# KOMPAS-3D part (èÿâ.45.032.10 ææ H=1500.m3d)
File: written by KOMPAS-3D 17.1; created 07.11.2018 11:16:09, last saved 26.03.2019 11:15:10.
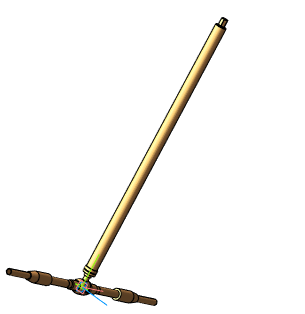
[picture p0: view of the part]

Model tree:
1. Операция без истории:2  (with: Сечение модели:1)  (labels: Сталь 20  ГОСТ 1050-2013)

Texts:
  Точка начала. Х
  Точка начала. Y
  Точка начала. Z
